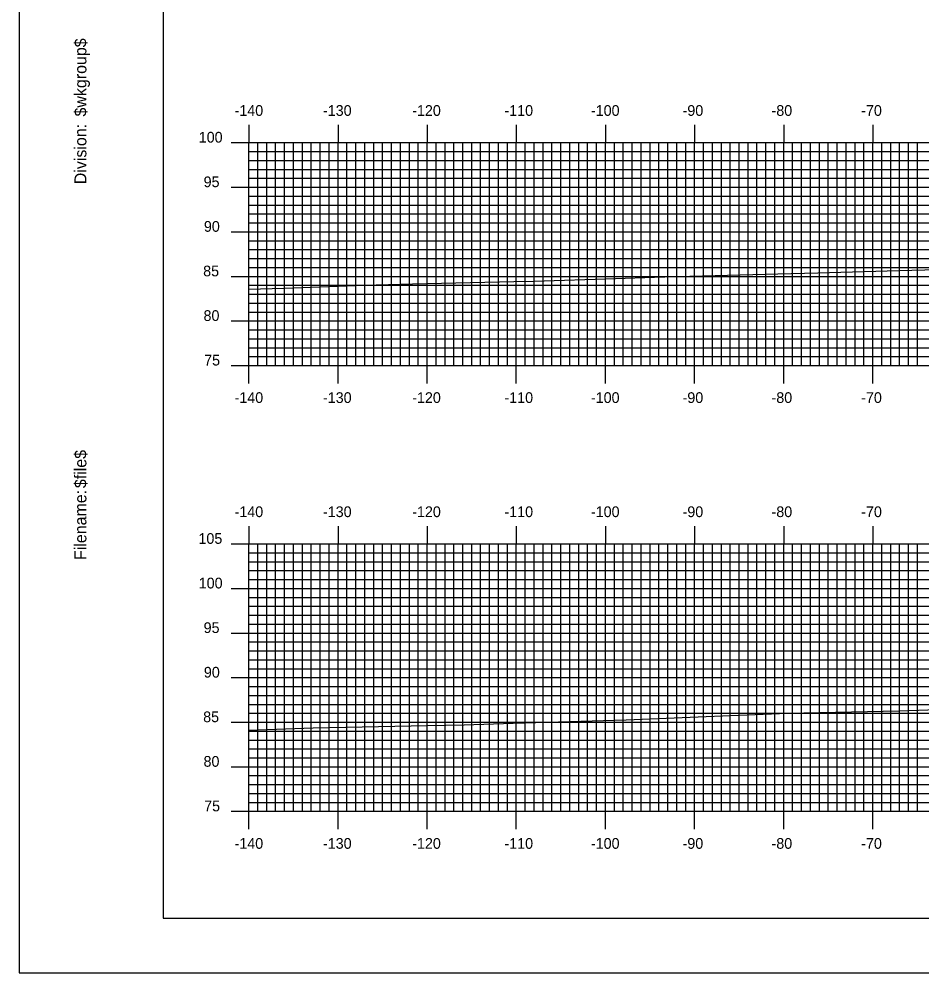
# Model space of a CAD drawing. Extents: x 1666 to 2009, y -1658 to -1438.
# Drawn here: x 1665.9 to 1767.2, y -1657.7 to -1550.7 of the extents above; entities that cross this region are included whole.
import ezdxf

# ---------------------------------------------------------------- set-up
doc = ezdxf.new("R2010")
doc.units = 0
for name, color, linetype in [('BORDER', 7, 'Continuous'), ('H_V ANNOTATION', 7, 'Continuous'), ('MAJOR', 7, 'Continuous'), ('MINOR', 7, 'Continuous'), ('PLOT BOUNDARY', 7, 'Continuous'), ('S_Roadway_Centerline', 7, 'Continuous')]:
    doc.layers.add(name, color=color, linetype=linetype)

msp = doc.modelspace()

# ---------------------------------------------------------------- linework, layer by layer
at = {"layer": 'BORDER'}
msp.add_lwpolyline([(1682.07, -1651.6), (2002.07, -1651.6), (2002.07, -1441.6), (1682.07, -1441.6)], close=True, dxfattribs=at)
at = {"layer": 'MAJOR'}
for p, q in [((1691.67, -1562.6), (1691.67, -1564.6)), ((1701.67, -1562.6), (1701.67, -1564.6)), ((1711.67, -1562.6), (1711.67, -1564.6)), ((1721.67, -1562.6), (1721.67, -1564.6)), ((1731.67, -1562.6), (1731.67, -1564.6)), ((1741.67, -1562.6), (1741.67, -1564.6)), ((1751.67, -1562.6), (1751.67, -1564.6)), ((1761.67, -1562.6), (1761.67, -1564.6)), ((1689.67, -1564.6), (1691.67, -1564.6)), ((1691.67, -1564.6), (1971.67, -1564.6)), ((1691.67, -1589.6), (1691.67, -1564.6)), ((1691.67, -1589.6), (1691.67, -1564.6)), ((1691.67, -1564.6), (1971.67, -1564.6)), ((1701.67, -1589.6), (1701.67, -1564.6)), ((1711.67, -1589.6), (1711.67, -1564.6)), ((1721.67, -1589.6), (1721.67, -1564.6)), ((1731.67, -1589.6), (1731.67, -1564.6)), ((1741.67, -1589.6), (1741.67, -1564.6)), ((1751.67, -1589.6), (1751.67, -1564.6)), ((1761.67, -1589.6), (1761.67, -1564.6)), ((1689.67, -1569.6), (1691.67, -1569.6)), ((1691.67, -1569.6), (1971.67, -1569.6)), ((1689.67, -1574.6), (1691.67, -1574.6)), ((1691.67, -1574.6), (1971.67, -1574.6)), ((1689.67, -1579.6), (1691.67, -1579.6)), ((1691.67, -1579.6), (1971.67, -1579.6)), ((1689.67, -1584.6), (1691.67, -1584.6)), ((1691.67, -1584.6), (1971.67, -1584.6)), ((1689.67, -1589.6), (1691.67, -1589.6)), ((1691.67, -1589.6), (1971.67, -1589.6)), ((1691.67, -1589.6), (1971.67, -1589.6)), ((1691.67, -1591.61), (1691.67, -1589.6)), ((1701.67, -1591.61), (1701.67, -1589.6)), ((1711.67, -1591.61), (1711.67, -1589.6)), ((1721.67, -1591.61), (1721.67, -1589.6)), ((1731.67, -1591.61), (1731.67, -1589.6)), ((1741.67, -1591.61), (1741.67, -1589.6)), ((1751.67, -1591.61), (1751.67, -1589.6)), ((1761.67, -1591.61), (1761.67, -1589.6)), ((1691.67, -1607.6), (1691.67, -1609.6)), ((1701.67, -1607.6), (1701.67, -1609.6)), ((1711.67, -1607.6), (1711.67, -1609.6)), ((1721.67, -1607.6), (1721.67, -1609.6)), ((1731.67, -1607.6), (1731.67, -1609.6)), ((1741.67, -1607.6), (1741.67, -1609.6)), ((1751.67, -1607.6), (1751.67, -1609.6)), ((1761.67, -1607.6), (1761.67, -1609.6)), ((1689.67, -1609.6), (1691.67, -1609.6)), ((1691.67, -1609.6), (1971.67, -1609.6)), ((1691.67, -1639.6), (1691.67, -1609.6)), ((1691.67, -1639.6), (1691.67, -1609.6)), ((1691.67, -1609.6), (1971.67, -1609.6)), ((1701.67, -1639.6), (1701.67, -1609.6)), ((1711.67, -1639.6), (1711.67, -1609.6)), ((1721.67, -1639.6), (1721.67, -1609.6)), ((1731.67, -1639.6), (1731.67, -1609.6)), ((1741.67, -1639.6), (1741.67, -1609.6)), ((1751.67, -1639.6), (1751.67, -1609.6)), ((1761.67, -1639.6), (1761.67, -1609.6)), ((1689.67, -1614.6), (1691.67, -1614.6)), ((1691.67, -1614.6), (1971.67, -1614.6)), ((1689.67, -1619.6), (1691.67, -1619.6)), ((1691.67, -1619.6), (1971.67, -1619.6)), ((1689.67, -1624.6), (1691.67, -1624.6)), ((1691.67, -1624.6), (1971.67, -1624.6)), ((1689.67, -1629.6), (1691.67, -1629.6)), ((1691.67, -1629.6), (1971.67, -1629.6)), ((1689.67, -1634.6), (1691.67, -1634.6)), ((1691.67, -1634.6), (1971.67, -1634.6)), ((1689.67, -1639.6), (1691.67, -1639.6)), ((1691.67, -1639.6), (1971.67, -1639.6)), ((1691.67, -1639.6), (1971.67, -1639.6)), ((1691.67, -1641.61), (1691.67, -1639.6)), ((1701.67, -1641.61), (1701.67, -1639.6)), ((1711.67, -1641.61), (1711.67, -1639.6)), ((1721.67, -1641.61), (1721.67, -1639.6)), ((1731.67, -1641.61), (1731.67, -1639.6)), ((1741.67, -1641.61), (1741.67, -1639.6)), ((1751.67, -1641.61), (1751.67, -1639.6)), ((1761.67, -1641.61), (1761.67, -1639.6))]:
    msp.add_line(p, q, dxfattribs=at)
at = {"layer": 'MINOR'}
for p, q in [((1692.67, -1589.6), (1692.67, -1564.6)), ((1693.67, -1589.6), (1693.67, -1564.6)), ((1694.67, -1589.6), (1694.67, -1564.6)), ((1695.67, -1589.6), (1695.67, -1564.6)), ((1696.67, -1589.6), (1696.67, -1564.6)), ((1697.67, -1589.6), (1697.67, -1564.6)), ((1698.67, -1589.6), (1698.67, -1564.6)), ((1699.67, -1589.6), (1699.67, -1564.6)), ((1700.67, -1589.6), (1700.67, -1564.6)), ((1702.67, -1589.6), (1702.67, -1564.6)), ((1703.67, -1589.6), (1703.67, -1564.6)), ((1704.67, -1589.6), (1704.67, -1564.6)), ((1705.67, -1589.6), (1705.67, -1564.6)), ((1706.67, -1589.6), (1706.67, -1564.6)), ((1707.67, -1589.6), (1707.67, -1564.6)), ((1708.67, -1589.6), (1708.67, -1564.6)), ((1709.67, -1589.6), (1709.67, -1564.6)), ((1710.67, -1589.6), (1710.67, -1564.6)), ((1712.67, -1589.6), (1712.67, -1564.6)), ((1713.67, -1589.6), (1713.67, -1564.6)), ((1714.67, -1589.6), (1714.67, -1564.6)), ((1715.67, -1589.6), (1715.67, -1564.6)), ((1716.67, -1589.6), (1716.67, -1564.6)), ((1717.67, -1589.6), (1717.67, -1564.6)), ((1718.67, -1589.6), (1718.67, -1564.6)), ((1719.67, -1589.6), (1719.67, -1564.6)), ((1720.67, -1589.6), (1720.67, -1564.6)), ((1722.67, -1589.6), (1722.67, -1564.6)), ((1723.67, -1589.6), (1723.67, -1564.6)), ((1724.67, -1589.6), (1724.67, -1564.6)), ((1725.67, -1589.6), (1725.67, -1564.6)), ((1726.67, -1589.6), (1726.67, -1564.6)), ((1727.67, -1589.6), (1727.67, -1564.6)), ((1728.67, -1589.6), (1728.67, -1564.6)), ((1729.67, -1589.6), (1729.67, -1564.6)), ((1730.67, -1589.6), (1730.67, -1564.6)), ((1732.67, -1589.6), (1732.67, -1564.6)), ((1733.67, -1589.6), (1733.67, -1564.6)), ((1734.67, -1589.6), (1734.67, -1564.6)), ((1735.67, -1589.6), (1735.67, -1564.6)), ((1736.67, -1589.6), (1736.67, -1564.6)), ((1737.67, -1589.6), (1737.67, -1564.6)), ((1738.67, -1589.6), (1738.67, -1564.6)), ((1739.67, -1589.6), (1739.67, -1564.6)), ((1740.67, -1589.6), (1740.67, -1564.6)), ((1742.67, -1589.6), (1742.67, -1564.6)), ((1743.67, -1589.6), (1743.67, -1564.6)), ((1744.67, -1589.6), (1744.67, -1564.6)), ((1745.67, -1589.6), (1745.67, -1564.6)), ((1746.67, -1589.6), (1746.67, -1564.6)), ((1747.67, -1589.6), (1747.67, -1564.6)), ((1748.67, -1589.6), (1748.67, -1564.6)), ((1749.67, -1589.6), (1749.67, -1564.6)), ((1750.67, -1589.6), (1750.67, -1564.6)), ((1752.67, -1589.6), (1752.67, -1564.6)), ((1753.67, -1589.6), (1753.67, -1564.6)), ((1754.67, -1589.6), (1754.67, -1564.6)), ((1755.67, -1589.6), (1755.67, -1564.6)), ((1756.67, -1589.6), (1756.67, -1564.6)), ((1757.67, -1589.6), (1757.67, -1564.6)), ((1758.67, -1589.6), (1758.67, -1564.6)), ((1759.67, -1589.6), (1759.67, -1564.6)), ((1760.67, -1589.6), (1760.67, -1564.6)), ((1762.67, -1589.6), (1762.67, -1564.6)), ((1763.67, -1589.6), (1763.67, -1564.6)), ((1764.67, -1589.6), (1764.67, -1564.6)), ((1765.67, -1589.6), (1765.67, -1564.6)), ((1766.67, -1589.6), (1766.67, -1564.6)), ((1691.67, -1565.6), (1971.67, -1565.6)), ((1691.67, -1565.6), (1693.68, -1565.6)), ((1691.67, -1566.6), (1971.67, -1566.6)), ((1691.67, -1566.6), (1693.68, -1566.6)), ((1691.67, -1567.6), (1971.67, -1567.6)), ((1691.67, -1567.6), (1693.68, -1567.6)), ((1691.67, -1568.6), (1971.67, -1568.6)), ((1691.67, -1568.6), (1693.68, -1568.6)), ((1691.67, -1570.6), (1971.67, -1570.6)), ((1691.67, -1570.6), (1693.68, -1570.6)), ((1691.67, -1571.6), (1971.67, -1571.6)), ((1691.67, -1571.6), (1693.68, -1571.6)), ((1691.67, -1572.6), (1971.67, -1572.6)), ((1691.67, -1572.6), (1693.68, -1572.6)), ((1691.67, -1573.6), (1971.67, -1573.6)), ((1691.67, -1573.6), (1693.68, -1573.6)), ((1691.67, -1575.6), (1971.67, -1575.6)), ((1691.67, -1575.6), (1693.68, -1575.6)), ((1691.67, -1576.6), (1971.67, -1576.6)), ((1691.67, -1576.6), (1693.68, -1576.6)), ((1691.67, -1577.6), (1971.67, -1577.6)), ((1691.67, -1577.6), (1693.68, -1577.6)), ((1691.67, -1578.6), (1971.67, -1578.6)), ((1691.67, -1578.6), (1693.68, -1578.6)), ((1691.67, -1580.6), (1971.67, -1580.6)), ((1691.67, -1580.6), (1693.68, -1580.6)), ((1691.67, -1581.6), (1971.67, -1581.6)), ((1691.67, -1581.6), (1693.68, -1581.6)), ((1691.67, -1582.6), (1971.67, -1582.6)), ((1691.67, -1582.6), (1693.68, -1582.6)), ((1691.67, -1583.6), (1971.67, -1583.6)), ((1691.67, -1583.6), (1693.68, -1583.6)), ((1691.67, -1585.6), (1971.67, -1585.6)), ((1691.67, -1585.6), (1693.68, -1585.6)), ((1691.67, -1586.6), (1971.67, -1586.6)), ((1691.67, -1586.6), (1693.68, -1586.6)), ((1691.67, -1587.6), (1971.67, -1587.6)), ((1691.67, -1587.6), (1693.68, -1587.6)), ((1691.67, -1588.6), (1971.67, -1588.6)), ((1691.67, -1588.6), (1693.68, -1588.6)), ((1692.67, -1639.6), (1692.67, -1609.6)), ((1693.67, -1639.6), (1693.67, -1609.6)), ((1694.67, -1639.6), (1694.67, -1609.6)), ((1695.67, -1639.6), (1695.67, -1609.6)), ((1696.67, -1639.6), (1696.67, -1609.6)), ((1697.67, -1639.6), (1697.67, -1609.6)), ((1698.67, -1639.6), (1698.67, -1609.6)), ((1699.67, -1639.6), (1699.67, -1609.6)), ((1700.67, -1639.6), (1700.67, -1609.6)), ((1702.67, -1639.6), (1702.67, -1609.6)), ((1703.67, -1639.6), (1703.67, -1609.6)), ((1704.67, -1639.6), (1704.67, -1609.6)), ((1705.67, -1639.6), (1705.67, -1609.6)), ((1706.67, -1639.6), (1706.67, -1609.6)), ((1707.67, -1639.6), (1707.67, -1609.6)), ((1708.67, -1639.6), (1708.67, -1609.6)), ((1709.67, -1639.6), (1709.67, -1609.6)), ((1710.67, -1639.6), (1710.67, -1609.6)), ((1712.67, -1639.6), (1712.67, -1609.6)), ((1713.67, -1639.6), (1713.67, -1609.6)), ((1714.67, -1639.6), (1714.67, -1609.6)), ((1715.67, -1639.6), (1715.67, -1609.6)), ((1716.67, -1639.6), (1716.67, -1609.6)), ((1717.67, -1639.6), (1717.67, -1609.6)), ((1718.67, -1639.6), (1718.67, -1609.6)), ((1719.67, -1639.6), (1719.67, -1609.6)), ((1720.67, -1639.6), (1720.67, -1609.6)), ((1722.67, -1639.6), (1722.67, -1609.6)), ((1723.67, -1639.6), (1723.67, -1609.6)), ((1724.67, -1639.6), (1724.67, -1609.6)), ((1725.67, -1639.6), (1725.67, -1609.6)), ((1726.67, -1639.6), (1726.67, -1609.6)), ((1727.67, -1639.6), (1727.67, -1609.6)), ((1728.67, -1639.6), (1728.67, -1609.6)), ((1729.67, -1639.6), (1729.67, -1609.6)), ((1730.67, -1639.6), (1730.67, -1609.6)), ((1732.67, -1639.6), (1732.67, -1609.6)), ((1733.67, -1639.6), (1733.67, -1609.6)), ((1734.67, -1639.6), (1734.67, -1609.6)), ((1735.67, -1639.6), (1735.67, -1609.6)), ((1736.67, -1639.6), (1736.67, -1609.6)), ((1737.67, -1639.6), (1737.67, -1609.6)), ((1738.67, -1639.6), (1738.67, -1609.6)), ((1739.67, -1639.6), (1739.67, -1609.6)), ((1740.67, -1639.6), (1740.67, -1609.6)), ((1742.67, -1639.6), (1742.67, -1609.6)), ((1743.67, -1639.6), (1743.67, -1609.6)), ((1744.67, -1639.6), (1744.67, -1609.6)), ((1745.67, -1639.6), (1745.67, -1609.6)), ((1746.67, -1639.6), (1746.67, -1609.6)), ((1747.67, -1639.6), (1747.67, -1609.6)), ((1748.67, -1639.6), (1748.67, -1609.6)), ((1749.67, -1639.6), (1749.67, -1609.6)), ((1750.67, -1639.6), (1750.67, -1609.6)), ((1752.67, -1639.6), (1752.67, -1609.6)), ((1753.67, -1639.6), (1753.67, -1609.6)), ((1754.67, -1639.6), (1754.67, -1609.6)), ((1755.67, -1639.6), (1755.67, -1609.6)), ((1756.67, -1639.6), (1756.67, -1609.6)), ((1757.67, -1639.6), (1757.67, -1609.6)), ((1758.67, -1639.6), (1758.67, -1609.6)), ((1759.67, -1639.6), (1759.67, -1609.6)), ((1760.67, -1639.6), (1760.67, -1609.6)), ((1762.67, -1639.6), (1762.67, -1609.6)), ((1763.67, -1639.6), (1763.67, -1609.6)), ((1764.67, -1639.6), (1764.67, -1609.6)), ((1765.67, -1639.6), (1765.67, -1609.6)), ((1766.67, -1639.6), (1766.67, -1609.6)), ((1691.67, -1610.6), (1971.67, -1610.6)), ((1691.67, -1610.6), (1693.68, -1610.6)), ((1691.67, -1611.6), (1971.67, -1611.6)), ((1691.67, -1611.6), (1693.68, -1611.6)), ((1691.67, -1612.6), (1971.67, -1612.6)), ((1691.67, -1612.6), (1693.68, -1612.6)), ((1691.67, -1613.6), (1971.67, -1613.6)), ((1691.67, -1613.6), (1693.68, -1613.6)), ((1691.67, -1615.6), (1971.67, -1615.6)), ((1691.67, -1615.6), (1693.68, -1615.6)), ((1691.67, -1616.6), (1971.67, -1616.6)), ((1691.67, -1616.6), (1693.68, -1616.6)), ((1691.67, -1617.6), (1971.67, -1617.6)), ((1691.67, -1617.6), (1693.68, -1617.6)), ((1691.67, -1618.6), (1971.67, -1618.6)), ((1691.67, -1618.6), (1693.68, -1618.6)), ((1691.67, -1620.6), (1971.67, -1620.6)), ((1691.67, -1620.6), (1693.68, -1620.6)), ((1691.67, -1621.6), (1971.67, -1621.6)), ((1691.67, -1621.6), (1693.68, -1621.6)), ((1691.67, -1622.6), (1971.67, -1622.6)), ((1691.67, -1622.6), (1693.68, -1622.6)), ((1691.67, -1623.6), (1971.67, -1623.6)), ((1691.67, -1623.6), (1693.68, -1623.6)), ((1691.67, -1625.6), (1971.67, -1625.6)), ((1691.67, -1625.6), (1693.68, -1625.6)), ((1691.67, -1626.6), (1971.67, -1626.6)), ((1691.67, -1626.6), (1693.68, -1626.6)), ((1691.67, -1627.6), (1971.67, -1627.6)), ((1691.67, -1627.6), (1693.68, -1627.6)), ((1691.67, -1628.6), (1971.67, -1628.6)), ((1691.67, -1628.6), (1693.68, -1628.6)), ((1691.67, -1630.6), (1971.67, -1630.6)), ((1691.67, -1630.6), (1693.68, -1630.6)), ((1691.67, -1631.6), (1971.67, -1631.6)), ((1691.67, -1631.6), (1693.68, -1631.6)), ((1691.67, -1632.6), (1971.67, -1632.6)), ((1691.67, -1632.6), (1693.68, -1632.6)), ((1691.67, -1633.6), (1971.67, -1633.6)), ((1691.67, -1633.6), (1693.68, -1633.6)), ((1691.67, -1635.6), (1971.67, -1635.6)), ((1691.67, -1635.6), (1693.68, -1635.6)), ((1691.67, -1636.6), (1971.67, -1636.6)), ((1691.67, -1636.6), (1693.68, -1636.6)), ((1691.67, -1637.6), (1971.67, -1637.6)), ((1691.67, -1637.6), (1693.68, -1637.6)), ((1691.67, -1638.6), (1971.67, -1638.6)), ((1691.67, -1638.6), (1693.68, -1638.6))]:
    msp.add_line(p, q, dxfattribs=at)
at = {"layer": 'PLOT BOUNDARY'}
msp.add_lwpolyline([(1665.89, -1657.72), (2005.89, -1657.72), (2005.89, -1437.72), (1665.89, -1437.72)], close=True, dxfattribs=at)
at = {"layer": 'S_Roadway_Centerline'}
for points in [[(1691.67, -1581.02), (1695.6, -1580.92), (1704.59, -1580.6), (1710.02, -1580.45), (1721.4, -1580.17), (1723.64, -1580.13), (1732.78, -1579.83), (1737.19, -1579.69), (1738.33, -1579.66), (1751, -1579.33), (1755.48, -1579.2), (1764.57, -1578.93), (1771.9, -1578.74)], [(1691.67, -1630.51), (1698.88, -1630.25), (1711.69, -1629.99), (1715.82, -1629.91), (1721.3, -1629.72), (1734.01, -1629.34), (1742.96, -1628.96), (1752.12, -1628.59), (1764.61, -1628.32), (1770, -1628.13), (1774.16, -1628), (1787.26, -1627.51), (1804.93, -1626.94), (1805.35, -1626.93), (1805.98, -1626.92), (1819.02, -1626.55), (1823.37, -1626.71), (1833.96, -1626.59), (1840.7, -1626.45), (1849.59, -1626.31), (1856.03, -1626.31), (1858.43, -1626.31), (1864.85, -1626.2), (1877.05, -1626.2)]]:
    msp.add_lwpolyline(points, dxfattribs=at)

# ---------------------------------------------------------------- texts
at = {"layer": 'BORDER'}
for s, p in [('$wkgroup$', (1673.44, -1561.67)), ('Division:', (1673.44, -1569.27)), ('$file$', (1673.44, -1603.35)), ('Filename:', (1673.44, -1611.41))]:
    msp.add_text(s, height=1.339, rotation=90, dxfattribs=at).set_placement(p)
at = {"layer": 'H_V ANNOTATION'}
for s, p in [('-140', (1690.06, -1561.6)), ('-130', (1699.98, -1561.6)), ('-120', (1709.99, -1561.6)), ('-110', (1720.34, -1561.6)), ('-100', (1730.04, -1561.6)), ('-90', (1740.32, -1561.6)), ('-80', (1750.3, -1561.6)), ('-70', (1760.36, -1561.6)), ('100', (1686.04, -1564.6)), ('95', (1686.59, -1569.6)), ('90', (1686.62, -1574.6)), ('85', (1686.54, -1579.6)), ('80', (1686.58, -1584.6)), ('75', (1686.65, -1589.6)), ('-140', (1690.06, -1593.8)), ('-130', (1699.98, -1593.8)), ('-120', (1709.99, -1593.8)), ('-110', (1720.34, -1593.8)), ('-100', (1730.04, -1593.8)), ('-90', (1740.32, -1593.8)), ('-80', (1750.3, -1593.8)), ('-70', (1760.36, -1593.8)), ('-140', (1690.06, -1606.6)), ('-130', (1699.98, -1606.6)), ('-120', (1709.99, -1606.6)), ('-110', (1720.34, -1606.6)), ('-100', (1730.04, -1606.6)), ('-90', (1740.32, -1606.6)), ('-80', (1750.3, -1606.6)), ('-70', (1760.36, -1606.6)), ('105', (1686.01, -1609.6)), ('100', (1686.04, -1614.6)), ('95', (1686.59, -1619.6)), ('90', (1686.62, -1624.6)), ('85', (1686.54, -1629.6)), ('80', (1686.58, -1634.6)), ('75', (1686.65, -1639.6)), ('-140', (1690.06, -1643.8)), ('-130', (1699.98, -1643.8)), ('-120', (1709.99, -1643.8)), ('-110', (1720.34, -1643.8)), ('-100', (1730.04, -1643.8)), ('-90', (1740.32, -1643.8)), ('-80', (1750.3, -1643.8)), ('-70', (1760.36, -1643.8))]:
    msp.add_text(s, height=1.2, dxfattribs=at).set_placement(p)
at = {"layer": 'MAJOR'}
for p in [(1691.66, -1589.6), (1691.66, -1639.6)]:
    msp.add_text('-', height=0.012, dxfattribs=at).set_placement(p)

doc.saveas('drawing.dxf')
